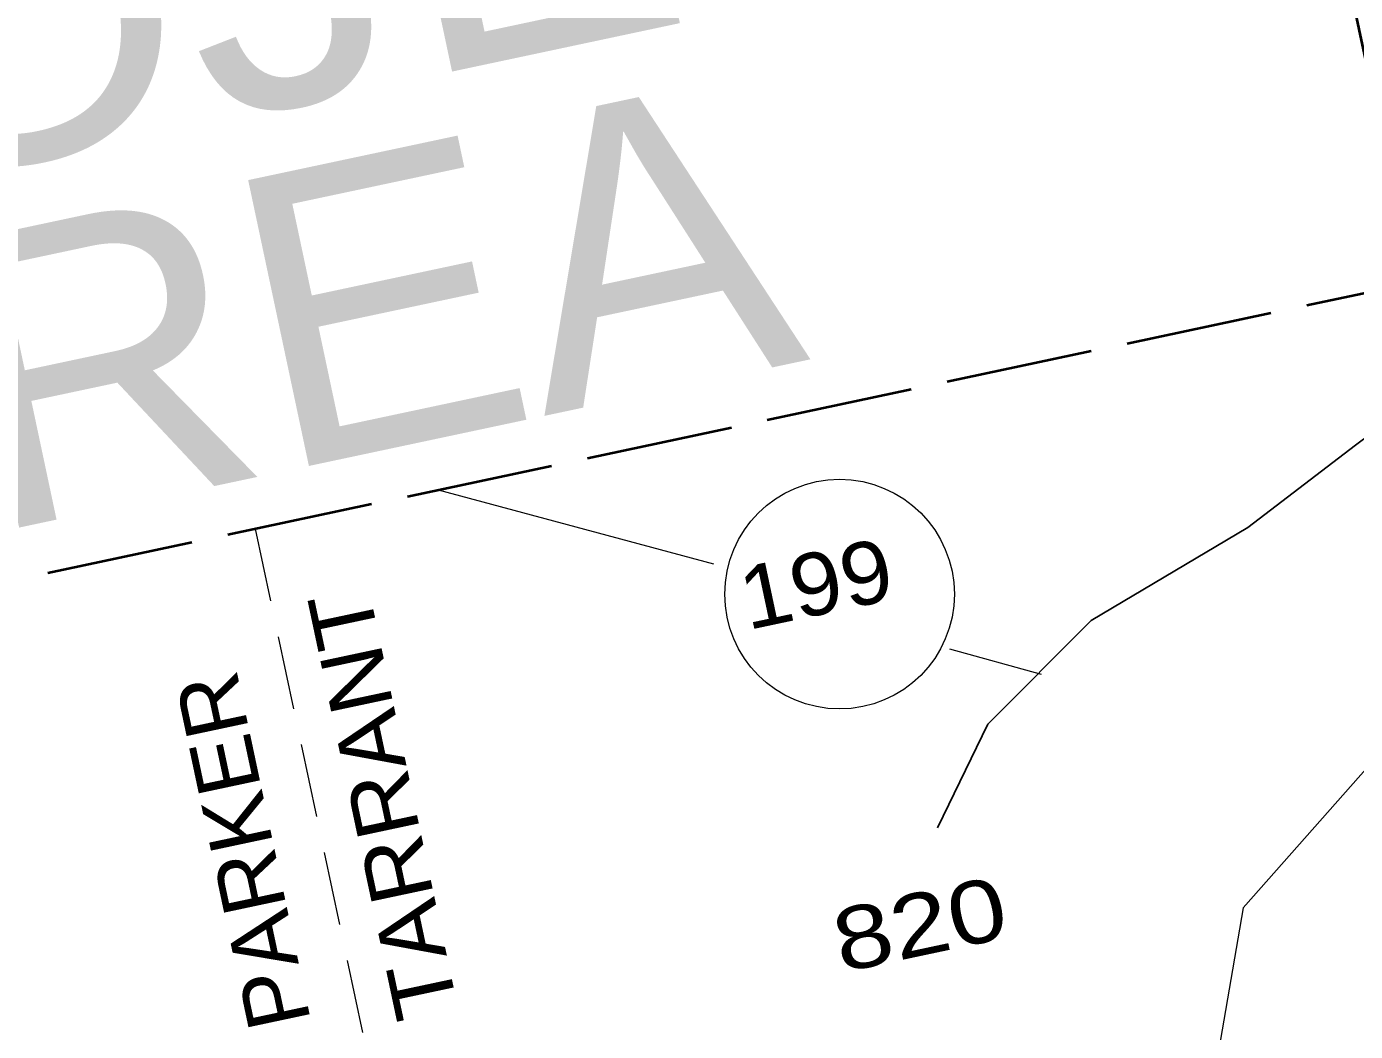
# Model space of a CAD drawing. Extents: x 2357218 to 2371708, y 6973728 to 6980157.
# Drawn here: x 2371276.8 to 2371385.2, y 6977607.1 to 6977689 of the extents above; entities that cross this region are included whole.
import ezdxf

# ---------------------------------------------------------------- set-up
doc = ezdxf.new("R2010")
doc.units = 0
doc.header["$LTSCALE"] = 2
doc.linetypes.add('LONG_DASHED', pattern=[7.5, 6, -1.5])
doc.linetypes.add('MEDIUM_DASHED', pattern=[4.5, 3, -1.5])
doc.layers.add('62', color=7, linetype='Continuous', lineweight=13)
doc.layers.add('63', color=7, linetype='Continuous', lineweight=13)

msp = doc.modelspace()

# ---------------------------------------------------------------- linework, layer by layer
at = {"layer": '62'}
for p, q in [((2371310.399, 6977651.227), (2371332.85, 6977645.188)), ((2371352.105, 6977638.262), (2371359.584, 6977636.191))]:
    msp.add_line(p, q, dxfattribs=at)
at = {"layer": '62', "linetype": 'MEDIUM_DASHED'}
msp.add_line((2371295.479, 6977648.054), (2371334.113, 6977466.412), dxfattribs=at)
at = {"layer": '62', "lineweight": 25}
msp.add_line((2371355.25, 6977632.119), (2371351.132, 6977623.675), dxfattribs=at)
at = {"layer": '62', "linetype": 'LONG_DASHED', "lineweight": 40}
msp.add_lwpolyline([(2371206.606, 6977694.407), (2371219.872, 6977631.985), (2371389.925, 6977668.131), (2371376.657, 6977730.551), (2371206.297, 6977694.341)], dxfattribs=at)
at = {"layer": '62', "lineweight": 25}
msp.add_lwpolyline([(2371355.25, 6977632.119), (2371363.665, 6977640.58), (2371376.434, 6977648.149), (2371385.219, 6977654.869), (2371394.06, 6977661.44), (2371404.933, 6977668.628), (2371411.105, 6977672.817), (2371420.879, 6977674.893), (2371436.483, 6977678.21), (2371448.589, 6977679.703), (2371454.984, 6977678.186), (2371458.397, 6977675.875)], dxfattribs=at)
at = {"layer": '62'}
msp.add_lwpolyline([(2371391.914, 6977635.059), (2371376.079, 6977617.133), (2371372.911, 6977598.812)], dxfattribs=at)
msp.add_circle((2371343.141, 6977642.721), 9.364, dxfattribs=at)
at = {"layer": '63'}
for p, q in [((2371310.399, 6977651.227), (2371332.85, 6977645.188)), ((2371352.105, 6977638.262), (2371359.584, 6977636.191))]:
    msp.add_line(p, q, dxfattribs=at)
at = {"layer": '63', "linetype": 'MEDIUM_DASHED'}
msp.add_line((2371295.479, 6977648.054), (2371334.113, 6977466.412), dxfattribs=at)
at = {"layer": '63', "lineweight": 25}
msp.add_line((2371355.25, 6977632.119), (2371351.132, 6977623.675), dxfattribs=at)
at = {"layer": '63', "linetype": 'LONG_DASHED', "lineweight": 40}
msp.add_lwpolyline([(2371206.606, 6977694.407), (2371219.872, 6977631.985), (2371389.925, 6977668.131), (2371376.657, 6977730.551), (2371206.297, 6977694.341)], dxfattribs=at)
at = {"layer": '63', "lineweight": 25}
msp.add_lwpolyline([(2371355.25, 6977632.119), (2371363.665, 6977640.58), (2371376.434, 6977648.149), (2371385.219, 6977654.869), (2371394.06, 6977661.44), (2371404.933, 6977668.628), (2371411.105, 6977672.817), (2371420.879, 6977674.893), (2371436.483, 6977678.21), (2371448.589, 6977679.703), (2371454.984, 6977678.186), (2371458.397, 6977675.875)], dxfattribs=at)
at = {"layer": '63'}
msp.add_lwpolyline([(2371391.914, 6977635.059), (2371376.079, 6977617.133), (2371372.911, 6977598.812)], dxfattribs=at)
msp.add_circle((2371343.141, 6977642.721), 9.364, dxfattribs=at)

# ---------------------------------------------------------------- texts
at = {"layer": '62'}
for s, height, rotation, width, p in [('PROJECT', 23.83, 12, 1.1, (2371217.279, 6977665.298)), ('AREA', 23.83, 12, 1.05, (2371251.706, 6977642.939)), ('199', 5.099, 12, 1.1, (2371335.632, 6977639.777)), ('TARRANT', 5.099, 102, 1.1, (2371312.068, 6977608.749)), ('PARKER', 5.099, 102, 1.05, (2371300.035, 6977607.893)), ('820', 5.099, 12, 1.25, (2371343.273, 6977611.839))]:
    msp.add_text(s, height=height, rotation=rotation, dxfattribs=dict(at, width=width)).set_placement(p)
at = {"layer": '63'}
for s, height, rotation, width, p in [('PROJECT', 23.83, 12, 1.1, (2371217.279, 6977665.298)), ('AREA', 23.83, 12, 1.05, (2371251.706, 6977642.939)), ('199', 5.099, 12, 1.1, (2371335.632, 6977639.777)), ('TARRANT', 5.099, 102, 1.1, (2371312.068, 6977608.749)), ('PARKER', 5.099, 102, 1.05, (2371300.035, 6977607.893)), ('820', 5.099, 12, 1.25, (2371343.273, 6977611.839))]:
    msp.add_text(s, height=height, rotation=rotation, dxfattribs=dict(at, width=width)).set_placement(p)

doc.saveas('drawing.dxf')
